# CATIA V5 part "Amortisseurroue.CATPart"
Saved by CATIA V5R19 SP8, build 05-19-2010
Part number: Amortisseurroue
Bounding box of the stored display mesh (mm): x 0 to 50, y -30 to 250, z -30 to 30
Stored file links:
  C:\Users\ThinkMotion\Desktop\EU_thinkMotion\iao\IAO_MMS_Groupe3\yschmidt\Train1434_yschmidt\Train1434_yschmidt\Amortisseurroue.CATPart
  C:\Users\ThinkMotion\Desktop\EU_thinkMotion\iao\IAO_MMS_Groupe3\yschmidt\Train1434_yschmidt\Train1434_yschmidt\AssemblageTrainOptimise.CATProduct
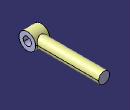
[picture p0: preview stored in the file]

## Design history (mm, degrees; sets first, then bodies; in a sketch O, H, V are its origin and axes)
Set1
  Plane1: linked copy from another document
  Point1: linked copy from another document
Body1 (main body)
  Sketch1 on yz-plane, origin (0, 0, 0), H (0, 1, 0), V (0, 0, 1)
    circle A1 centre (0, 0) radius 30
    reference projected point E1 (0, 0) from Point1
    radius A1 = 30
    concentricity: E1 A1
  Pad1: profile Sketch1, direction (1, 0, 0), length 50
  Sketch2 on zx-plane, origin (0, 0, 0), H (-1, 0, 0), V (0, 0, 1)
    circle A1 centre (-25, 0) radius 20
    point P1 (-25, 0)
    reference projected line E1 (0, -30) -> (0, 30) from edge [start face of Pad1 | face of Pad1 from Sketch1.A1]
    radius A1 = 20
    distance P1 E1 = 25
    coincidence: P1 H
  Pad2: profile Sketch2, direction (0, 1, 0), up to Plane1
  Sketch3 on start face of Pad1, origin (0, 0, 0), H (0, 1, 0), V (0, 0, -1)
    point P1 (0, 0)
    reference projected point E1 (0, 0) from Point1
    coincidence: P1 E1
  Hole1: placed by Sketch3, at (0, 0, 0) direction (1, 0, 0), diameter 30, through (limit type 6)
